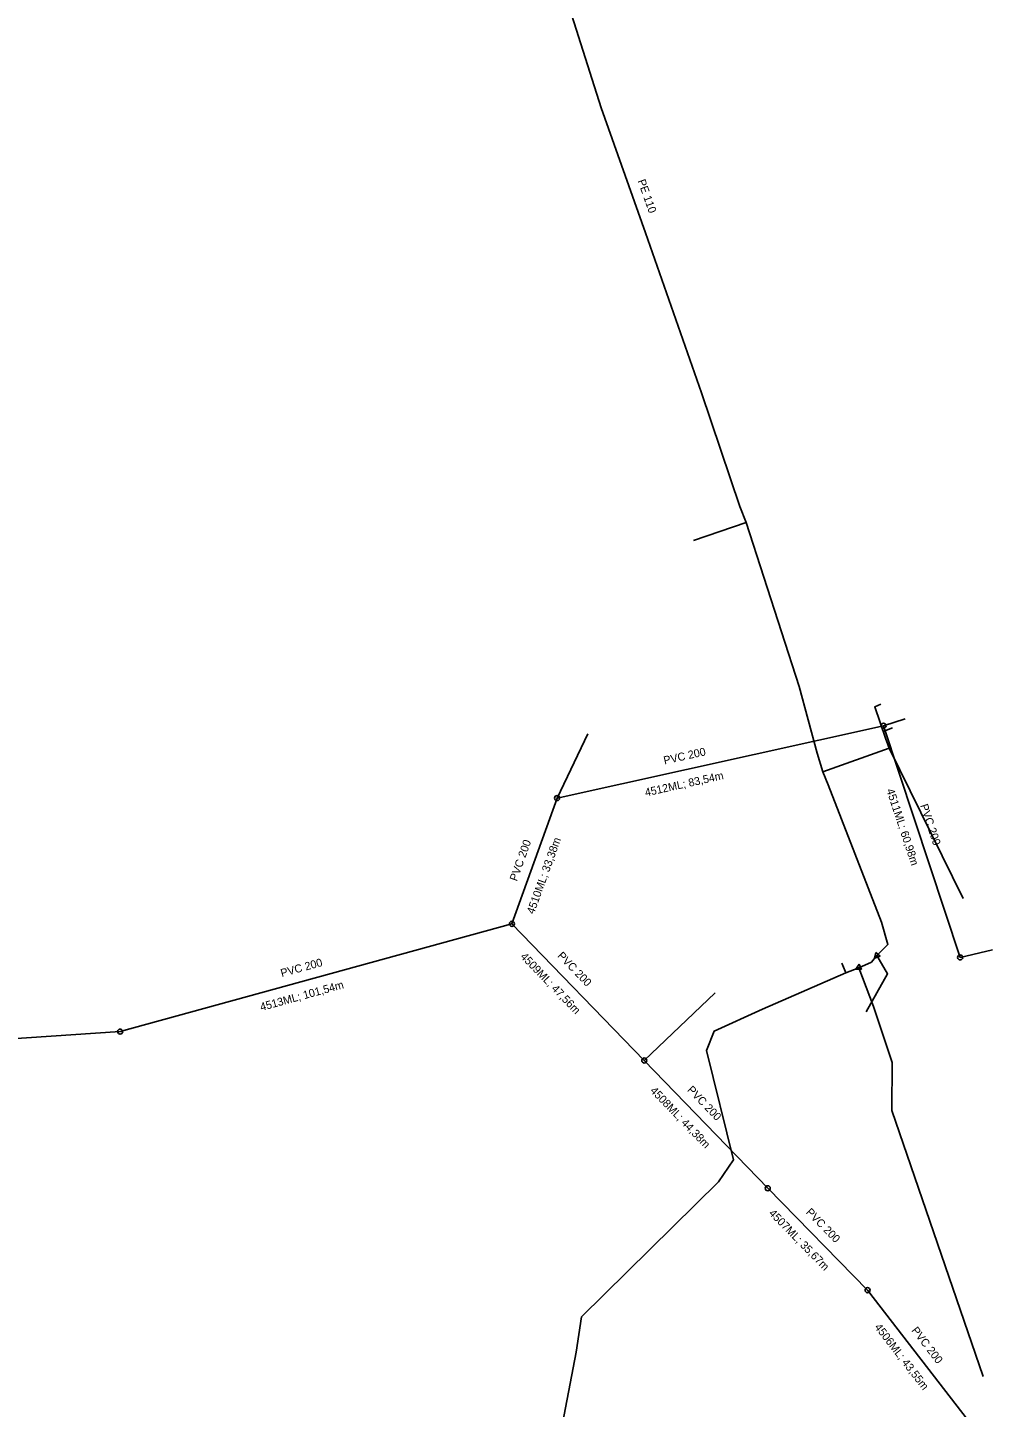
# Model space of a CAD drawing. Extents: x -867696 to -865033, y -1042522 to -1039817.
# Drawn here: x -865425.8 to -865184.7, y -1040899.3 to -1040554.5 of the extents above; entities that cross this region are included whole.
import ezdxf

# ---------------------------------------------------------------- set-up
doc = ezdxf.new("R2010")
doc.units = 0
for name, color, linetype in [('KN - popis material', 7, 'Continuous'), ('KN - popis usek delka', 7, 'Continuous'), ('KN - pripojka', 7, 'Continuous'), ('KN - sachta komora', 7, 'Continuous'), ('KN - splaskova', 7, 'Continuous'), ('Level 1', 7, 'Continuous'), ('V - ostatni', 7, 'Continuous'), ('V - popis material', 7, 'Continuous'), ('V - pripojka', 7, 'Continuous'), ('V - rozvadeci', 7, 'Continuous')]:
    doc.layers.add(name, color=color, linetype=linetype)

# ---------------------------------------------------------------- blocks, each defined once
blk = doc.blocks.new('100.M')
at = {"layer": 'Level 1'}
blk.add_circle((0, 0), 1.27, dxfattribs=at)
blk = doc.blocks.new('111')
at = {"layer": 'Level 1'}
for p, q in [((0.42, 0.72), (-0.83, 0)), ((-0.83, 0), (0.42, -0.72)), ((0.42, -0.72), (0.42, 0.72))]:
    blk.add_line(p, q, dxfattribs=at)

msp = doc.modelspace()

# ---------------------------------------------------------------- linework, layer by layer
at = {"layer": 'KN - pripojka'}
for points in [[(-865211.891, -1040728.976), (-865206.44, -1040727.213)], [(-865293.454, -1040747.06), (-865285.792, -1040731.03)], [(-865192.735, -1040786.868), (-865184.68, -1040784.94)], [(-865271.663, -1040812.636), (-865253.93, -1040795.71)]]:
    msp.add_lwpolyline(points, dxfattribs=at)
at = {"layer": 'KN - splaskova'}
for points in [[(-865211.891, -1040728.976), (-865293.454, -1040747.06)], [(-865192.735, -1040786.868), (-865211.891, -1040728.976)], [(-865304.744, -1040778.47), (-865293.454, -1040747.06)], [(-865304.744, -1040778.47), (-865402.644, -1040805.416)], [(-865271.663, -1040812.636), (-865304.744, -1040778.47)], [(-865402.644, -1040805.416), (-865485.246, -1040810.93)], [(-865240.825, -1040844.549), (-865271.663, -1040812.636)], [(-865215.862, -1040870.025), (-865240.825, -1040844.549)], [(-865189.246, -1040904.495), (-865215.862, -1040870.025)]]:
    msp.add_lwpolyline(points, dxfattribs=at)
at = {"layer": 'V - pripojka'}
for points in [[(-865246.19, -1040678.18), (-865259.41, -1040682.704)], [(-865210.503, -1040734.579), (-865211.382, -1040732.077), (-865214.09, -1040724.224), (-865212.6, -1040723.547)], [(-865211.961, -1040730.398), (-865209.616, -1040729.478)], [(-865227.07, -1040740.53), (-865210.503, -1040734.579)], [(-865210.503, -1040734.579), (-865192.02, -1040772.156)], [(-865221.302, -1040790.746), (-865221.49, -1040790.34), (-865222.334, -1040788.309)], [(-865213.55, -1040786.42), (-865210.872, -1040790.999), (-865216.256, -1040800.454)], [(-865218.08, -1040789.44), (-865214.418, -1040799.162), (-865209.694, -1040813.172), (-865209.787, -1040825.162), (-865186.995, -1040891.583)]]:
    msp.add_lwpolyline(points, dxfattribs=at)
at = {"layer": 'V - rozvadeci'}
for points in [[(-865213.55, -1040786.42), (-865210.77, -1040783.68), (-865212.42, -1040778.09), (-865225.69, -1040743.72), (-865227.07, -1040740.53), (-865228.47, -1040735.82), (-865233, -1040719.19), (-865246.19, -1040678.18), (-865247.8, -1040674.16), (-865257.39, -1040645.74), (-865271.34, -1040605.79), (-865282.43, -1040574.59), (-865290.91, -1040547.84), (-865294.17, -1040535.46), (-865300.81, -1040532.21), (-865303.96, -1040513.6), (-865306.62, -1040494.99), (-865310.4, -1040476.96)], [(-865213.55, -1040786.42), (-865214.92, -1040788.07), (-865218.08, -1040789.44)], [(-865218.08, -1040789.44), (-865221.302, -1040790.746), (-865242.12, -1040799.77), (-865254.24, -1040805.3), (-865256.14, -1040810.11), (-865249.4, -1040837.49), (-865253.1, -1040842.97), (-865287.39, -1040876.73), (-865288.71, -1040885.55), (-865292.82, -1040907.3), (-865299.09, -1040929.21), (-865304.16, -1040948.97), (-865313.2, -1040983.18), (-865320.84, -1041015.47), (-865330.84, -1041057.71), (-865337.42, -1041087.21), (-865345.33, -1041121.67), (-865351.4, -1041149.61), (-865359.29, -1041177.45), (-865364.92, -1041195.75), (-865366.18, -1041200.61), (-865367.07, -1041205.82), (-865365.16, -1041210.96), (-865359.01, -1041217.82)]]:
    msp.add_lwpolyline(points, dxfattribs=at)

# ---------------------------------------------------------------- block references
at = {"layer": 'KN - sachta komora'}
for p, xscale, yscale, rotation in [((-865211.891, -1040728.976), 0.5018521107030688, 0.5018521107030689, 150.62079160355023), ((-865293.454, -1040747.06), 0.5000000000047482, 0.5000000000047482, -137.9999986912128), ((-865304.744, -1040778.47), 0.4999999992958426, 0.4999999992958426, 103.00000027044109), ((-865192.735, -1040786.868), 0.4999999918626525, 0.4999999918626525, 109.00000122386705), ((-865402.644, -1040805.416), 0.5036654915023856, 0.5036654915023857, -167.86109133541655), ((-865271.663, -1040812.636), 0.4999999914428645, 0.49999999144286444, 135), ((-865240.825, -1040844.549), 0.4999999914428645, 0.49999999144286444, 135), ((-865215.862, -1040870.025), 0.5000000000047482, 0.5000000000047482, 132.0000013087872)]:
    msp.add_blockref('100.M', p, dxfattribs=dict(at, xscale=xscale, yscale=yscale, rotation=rotation))
at = {"layer": 'V - ostatni'}
for p, xscale, yscale, rotation in [((-865213.55, -1040786.42), 1.0000000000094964, 1.0000000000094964, 47.99999869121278), ((-865218.08, -1040789.44), 1.0225848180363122, 1.0225848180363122, 25.81897435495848)]:
    msp.add_blockref('111', p, dxfattribs=dict(at, xscale=xscale, yscale=yscale, rotation=rotation))

# ---------------------------------------------------------------- texts
at = {"layer": 'KN - popis material'}
for rotation, p in [(12.5, (-865266.618, -1040738.651)), (288.31, (-865202.772, -1040748.894)), (70.23, (-865303.52, -1040767.971)), (314.08, (-865293.517, -1040786.615)), (15.39, (-865362.251, -1040791.809)), (314.02, (-865261.082, -1040820.133)), (314.42, (-865231.431, -1040850.707)), (307.67, (-865205.022, -1040880.135))]:
    msp.add_text('PVC 200', height=2, rotation=rotation, dxfattribs=at).set_placement(p)
at = {"layer": 'KN - popis usek delka'}
for s, rotation, p in [('4512ML; 83,54m', 12.5, (-865271.297, -1040746.654)), ('4511ML; 60,98m', 288.31, (-865211.207, -1040745.05)), ('4510ML; 33,38m', 70.23, (-865299.252, -1040776.2)), ('4509ML; 47,56m', 314.08, (-865302.785, -1040786.819)), ('4513ML; 101,54m', 15.39, (-865367.388, -1040800.276)), ('4508ML; 44,38m', 314.02, (-865270.35, -1040820.327)), ('4507ML; 35,67m', 314.42, (-865240.697, -1040850.968)), ('4506ML; 43,55m', 307.67, (-865214.255, -1040879.304))]:
    msp.add_text(s, height=1.99999, rotation=rotation, dxfattribs=at).set_placement(p)
at = {"layer": 'V - popis material'}
msp.add_text('PE 110', height=2, rotation=289.57, dxfattribs=at).set_placement((-865273.368, -1040592.807))

doc.saveas('drawing.dxf')
